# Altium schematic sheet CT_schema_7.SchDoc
size 287 x 160 mm
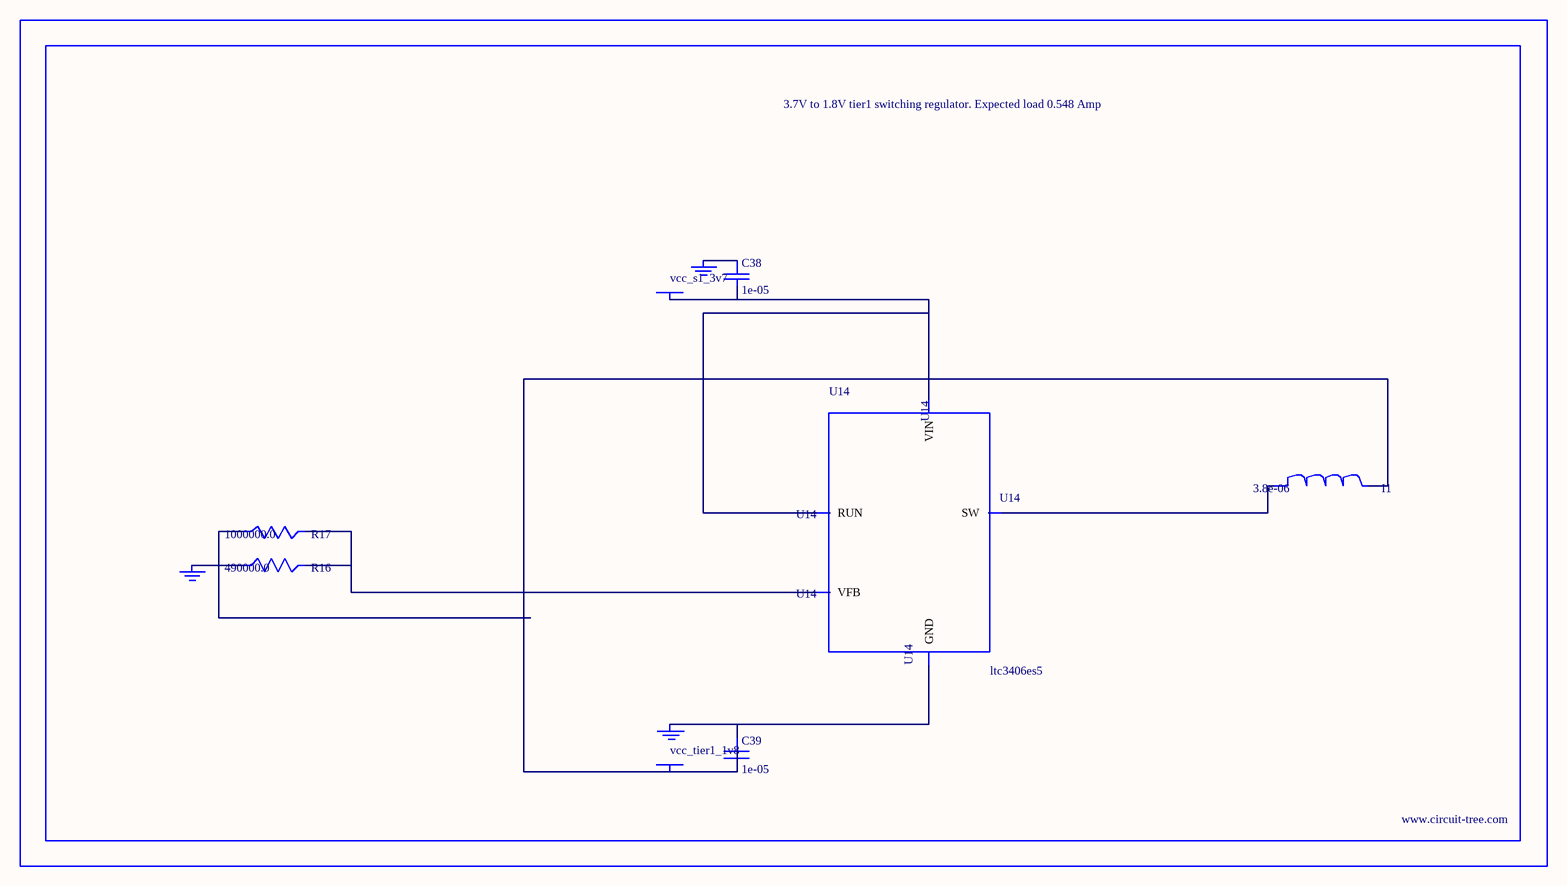
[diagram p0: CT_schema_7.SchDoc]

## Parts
BORDER6  (no value)
C38  1e-05  [C0805]
C39  1e-05  [C0805]
GND_INSTANCE_6_0  (no value)
GND_INSTANCE_6_1  (no value)
GND_INSTANCE_6_2  (no value)
I1  3.8e-06  [DR1040]
POWER_INSTANCE_6_0  vcc_tier1_1v8
POWER_INSTANCE_6_1  vcc_s1_3v7
R16  490000.0  [R0603]
R17  1000000.0  [R0603]
U14  ltc3406es5  [TSOT-23-5]

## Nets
NetC38_1: C38.1 GND_INSTANCE_6_1.0(GND)
NetC38_2: C38.2 POWER_INSTANCE_6_1.0(PWR) U14.1(RUN) U14.4(VIN)
NetC39_1: C39.1 GND_INSTANCE_6_0.0(GND) U14.2(GND)
NetC39_2: C39.2 I1.2 POWER_INSTANCE_6_0.0(PWR) R17.1
NetGND_INSTANCE_6_2_0: GND_INSTANCE_6_2.0(GND) R16.1
NetI1_1: I1.1 U14.3(SW)
NetR16_2: R16.2 R17.2 U14.5(VFB)

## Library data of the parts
BORDER6 = BORDER_PAGE6
C38 C39 = C0805C106K8RACTU
GND_INSTANCE_6_0-GND_INSTANCE_6_2 = GND
I1 = DR1040-3R8-R
POWER_INSTANCE_6_0 POWER_INSTANCE_6_1 = PWR
R16 = R16
R17 = RC0603JR-071ML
